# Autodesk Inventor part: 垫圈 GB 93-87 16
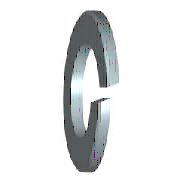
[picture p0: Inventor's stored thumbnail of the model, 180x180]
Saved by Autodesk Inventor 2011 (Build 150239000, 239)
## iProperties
Created: 2010-02
Part Number: 垫圈 GB 93-87 16
Material: 低炭钢
Description: 单弹簧锁紧垫圈，普通型
Document SubType Name: Modeling
Standard: GB/T 93-1987
Designer: Administrator
Standard Revision: 1987
Standards Organization: GB
Language: zh-CN
Size Designation: M16
Categories: <MemberInstance><Categories><Category DisplayName="紧固件" InternalName="e4da775c-781d-43d5-af7c-5136215cf5a6" Mnemonic="FSTN"><Category DisplayName="垫圈" InternalN
Density: 1 g/cm^3
IsCustomPart: 1
Author: Administrator
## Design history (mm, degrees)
body "Solid1"
sketch "Sketch1"
  geometry: C1 r 12.2 at (0, 0); C2 r 8.1 at (0, 0); 1 further point
  constraints: 2 centre point, 2 coincident
  dimensions: "d0" = 16.2 diameter of C2 (= SD1); "d1" = 24.4 diameter of C1 (= SD2)
extrude "Body" new body sketch "Sketch1" distance "d2" = 4.1 (= SD); taper "d3" = 0 deg
sketch "Sketch2"
  geometry: L1 (0, -8.1)-(0, 8.1) reference; L2 (4.1, 12.2)-(4.1, -12.2) reference; L3 (-1.2, 0)-(7.2, 0) reference; L4 (0, -0.82)-(4.1, 0.512); L5 (0, 0.82)-(4.1, 2.152)
  constraints: 4 end point, 4 point on line, 1 parallel
  dimensions: "d4" = 0.82 distance from line of L3 L4.start (= 0.2 x SD); "d5" = 0.82 distance from line of L3 L5.start (= 0.2 x SD); "d6" = 72 deg angle of L2 L4 (= FAWI)
extrude "Cut" cut sketch "Sketch2" stored distance "d7" = 4.1 (= SD); taper "d8" = 0 deg
workaxis "Work Axis1"
workplane "Work Plane1"
other parameters: "SD1" = 16.2 [user parameter; used in 1 equation term], "SD2" = 24.4 [user parameter; used in 1 equation term], "SD" = 4.1 [user parameter; used in 4 equation terms], "FAWI" = 72 deg [user parameter; used in 1 equation term], "d9" = 0, "d10" = 0, "d11" = 0, "d12" = 0, "NND" = 16 [user parameter]
